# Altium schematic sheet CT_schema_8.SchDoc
size 391 x 238 mm
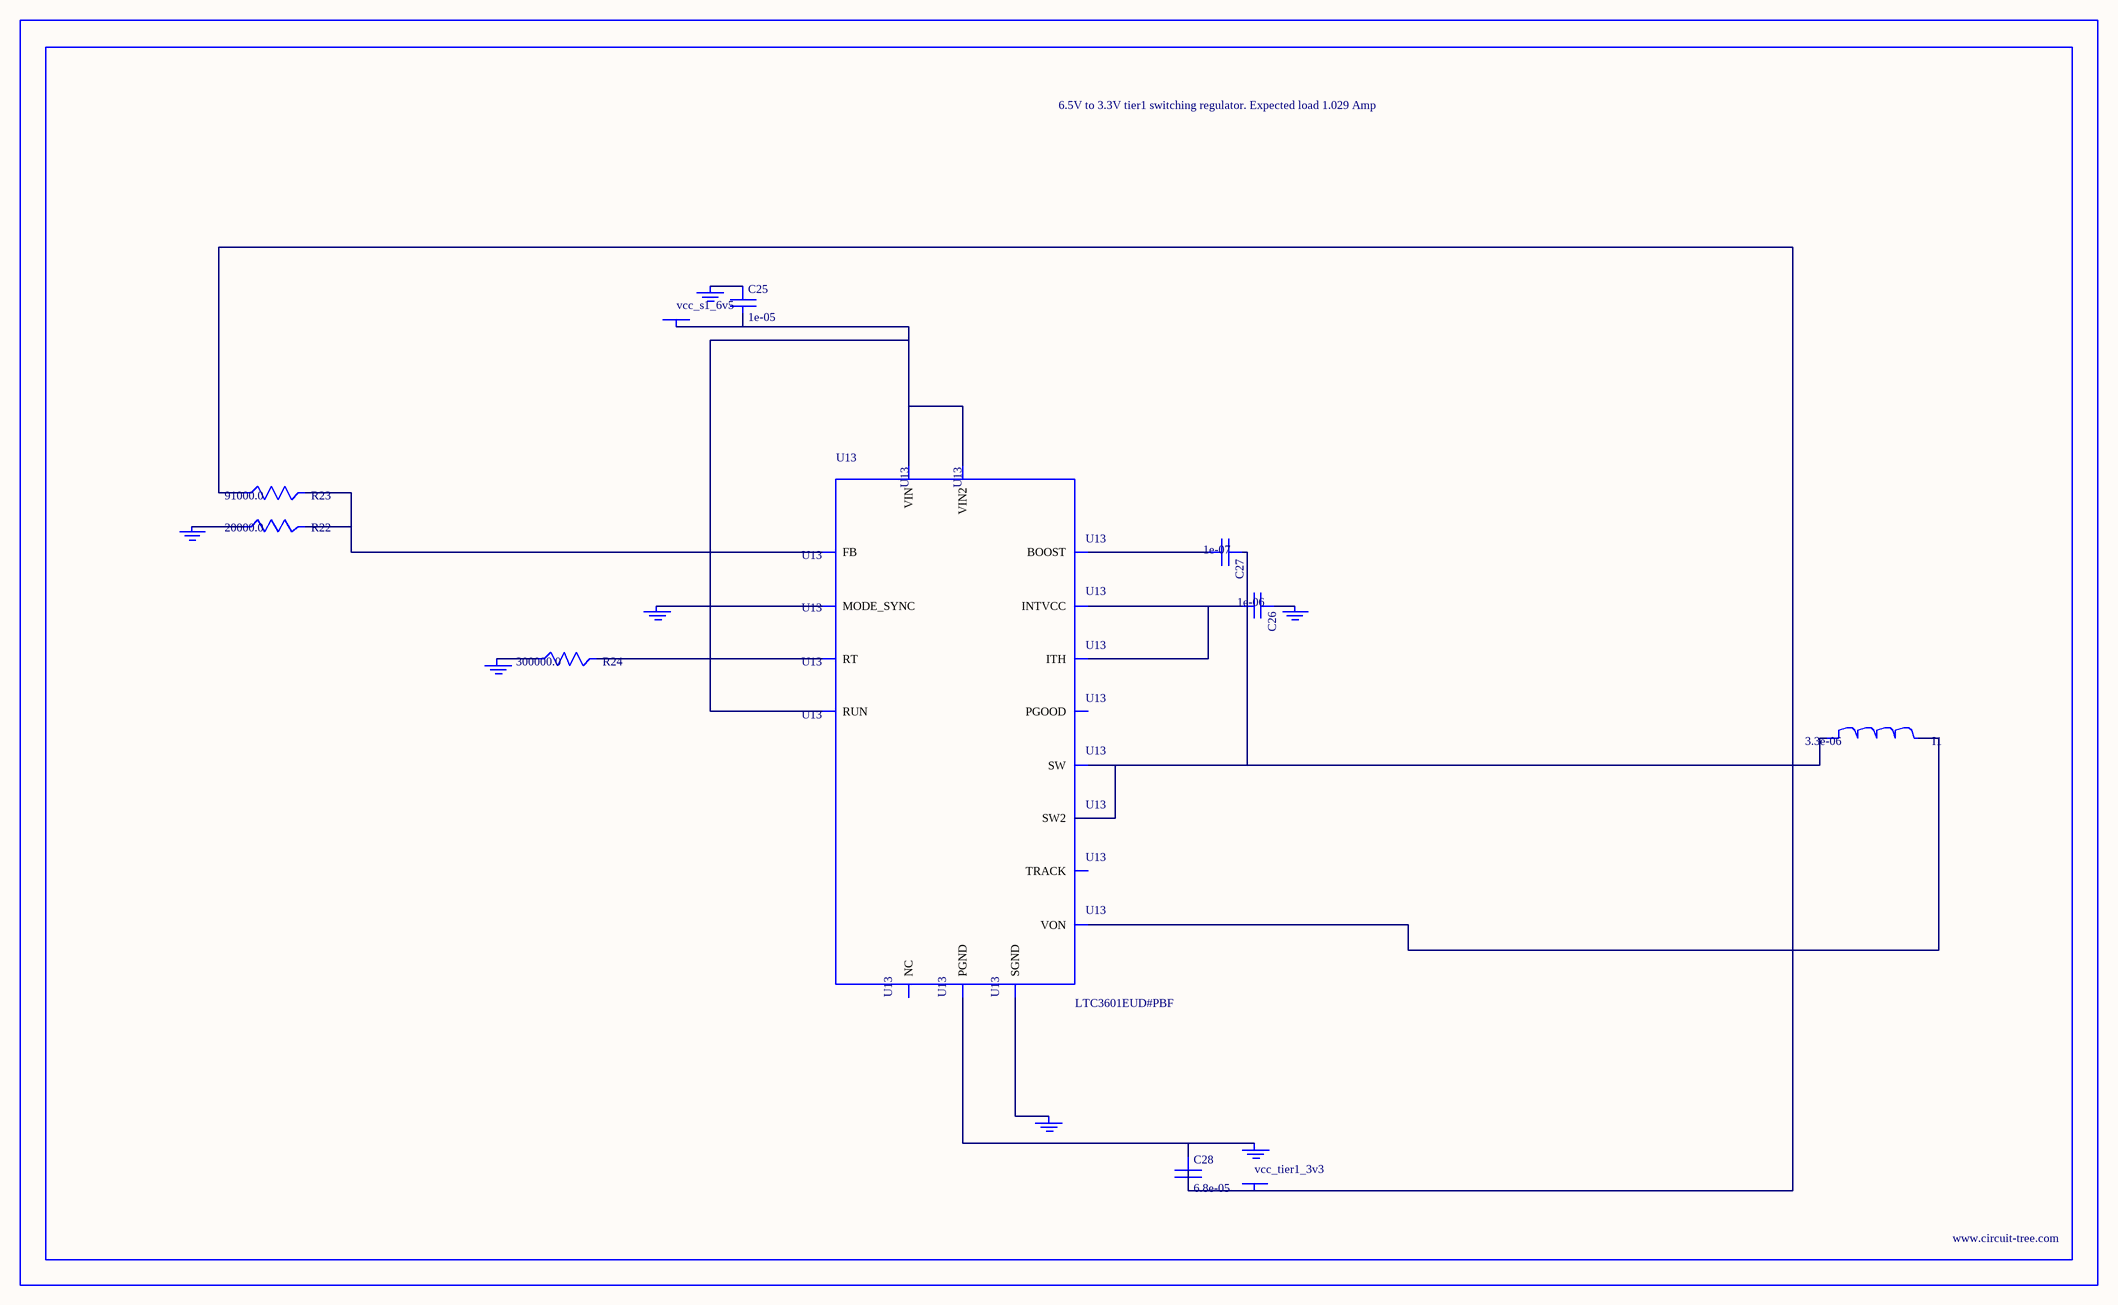
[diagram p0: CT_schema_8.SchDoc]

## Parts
BORDER7  (no value)
C25  1e-05  [C0805]
C26  1e-06  [C0603]
C27  1e-07  [C0402]
C28  6.8e-05  [2220]
GND_INSTANCE_7_0  (no value)
GND_INSTANCE_7_1  (no value)
GND_INSTANCE_7_2  (no value)
GND_INSTANCE_7_3  (no value)
GND_INSTANCE_7_4  (no value)
GND_INSTANCE_7_5  (no value)
GND_INSTANCE_7_6  (no value)
I1  3.3e-06  [WE-HCI_7030/7040/7050]
POWER_INSTANCE_7_0  vcc_s1_6v5
POWER_INSTANCE_7_1  vcc_tier1_3v3
R22  20000.0  [R0603]
R23  91000.0  [R0603]
R24  300000.0  [R0603]
U13  LTC3601EUD#PBF  [QFN-16_EP]

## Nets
NetC25_1: C25.1 GND_INSTANCE_7_5.0(GND)
NetC25_2: C25.2 POWER_INSTANCE_7_0.0(PWR) U13.14(RUN) U13.15(VIN) U13.16(VIN2)
NetC26_1: C26.1 GND_INSTANCE_7_1.0(GND)
NetC26_2: C26.2 U13.7(INTVCC) U13.12(ITH)
NetC27_1: C27.1 I1.1 U13.3(SW) U13.4(SW2)
NetC27_2: C27.2 U13.6(BOOST)
NetC28_1: C28.1 GND_INSTANCE_7_6.0(GND) U13.17(PGND)
NetC28_2: C28.2 I1.2 POWER_INSTANCE_7_1.0(PWR) R23.1 U13.8(VON)
NetGND_INSTANCE_7_0_0: GND_INSTANCE_7_0.0(GND) U13.1(MODE_SYNC)
NetGND_INSTANCE_7_2_0: GND_INSTANCE_7_2.0(GND) U13.9(SGND)
NetGND_INSTANCE_7_3_0: GND_INSTANCE_7_3.0(GND) R24.1
NetGND_INSTANCE_7_4_0: GND_INSTANCE_7_4.0(GND) R22.1
NetR22_2: R22.2 R23.2 U13.11(FB)
NetR24_2: R24.2 U13.10(RT)

Not connected (* = marked no-connect by the designer): U13 2(PGOOD) 5(NC) 13(TRACK)

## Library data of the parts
BORDER7 = BORDER_PAGE7
C25 = C0805C106K8RACTU
C26 = C0603C105K3RACTU
C27 = C0402C104K3RACTU
C28 = C5750X5R1A686M
GND_INSTANCE_7_0-GND_INSTANCE_7_6 = GND
I1 = 744314330
POWER_INSTANCE_7_0 POWER_INSTANCE_7_1 = PWR
R22 = RC0603JR-0720KL
R23 = RC0603JR-0791KL
R24 = RC0603JR-07300KL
